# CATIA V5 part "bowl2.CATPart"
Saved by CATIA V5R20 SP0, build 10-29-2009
Part number: bowl2
Material "Grey Blue": density 7860 kg/m3, Young's modulus 2e+11 Pa, Poisson ratio 0.266
Bounding box of the stored display mesh (mm): x -60 to 60, y -60 to 59.999, z 0 to 40
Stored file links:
  E:\设计\180212313林恺昇\bowl2.CATPart
  E:\设计\180212313林恺昇\Product1.CATProduct
  E:\设计\180212313林恺昇\cart3.CATPart
  C:\Program Files\Dassault Systemes\B20\intel_a\startup\materials\Catalog.CATMaterial
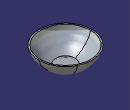
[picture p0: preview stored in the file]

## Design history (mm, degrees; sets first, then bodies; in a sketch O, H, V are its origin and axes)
Body1 (main body)
  Sketch1 on xy-plane, origin (0, 0, 0), H (1, 0, 0), V (0, 1, 0)
    circle A1 centre (0, 0) radius 22.5
    radius A1 = 22.5
  Plane1: type Offset, RefPlane xy-plane, Offset 10
  Plane2: type Offset, RefPlane Plane1, Offset 10
  Plane3: type Offset, RefPlane Plane2, Offset 10
  Plane4: type Offset, RefPlane Plane3, Offset 10
  Sketch2 on Plane4, origin (0, 0, 40), H (1, 0, 0), V (0, 1, 0)
    circle A1 centre (0, 0) radius 60
    radius A1 = 60
  Sketch3 on Plane3, origin (0, 0, 30), H (1, 0, 0), V (0, 1, 0)
    circle A1 centre (0, 0) radius 56.5
    radius A1 = 56.5
  Sketch4 on Plane2, origin (0, 0, 20), H (1, 0, 0), V (0, 1, 0)
    circle A1 centre (0, 0) radius 49
    radius A1 = 49
  Sketch5 on Plane1, origin (0, 0, 10), H (1, 0, 0), V (0, 1, 0)
    circle A1 centre (0, 0) radius 40
    radius A1 = 40
  Loft1: solid, Sections (Sketch2; Sketch3; Sketch4; Sketch5; Sketch1)
  Shell1: ExtOffset 0, Face face of Loft1, IntOffset 3
  Sketch6 on face of Loft1, origin (0, 0, 0), H (1, 0, 0), V (0, -1, 0)
    circle A1 centre (0, 0) radius 20
    radius A1 = 20
  Pocket1: profile Sketch6, direction (0, 0, 1), length 2
  Fillet1: radius 1, on edge [face of Pocket1 from Sketch6.A1 | end face of Pocket1]
  Fillet2: radius 1, on edge [face of Loft1 | face of Pocket1 from Sketch6.A1]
